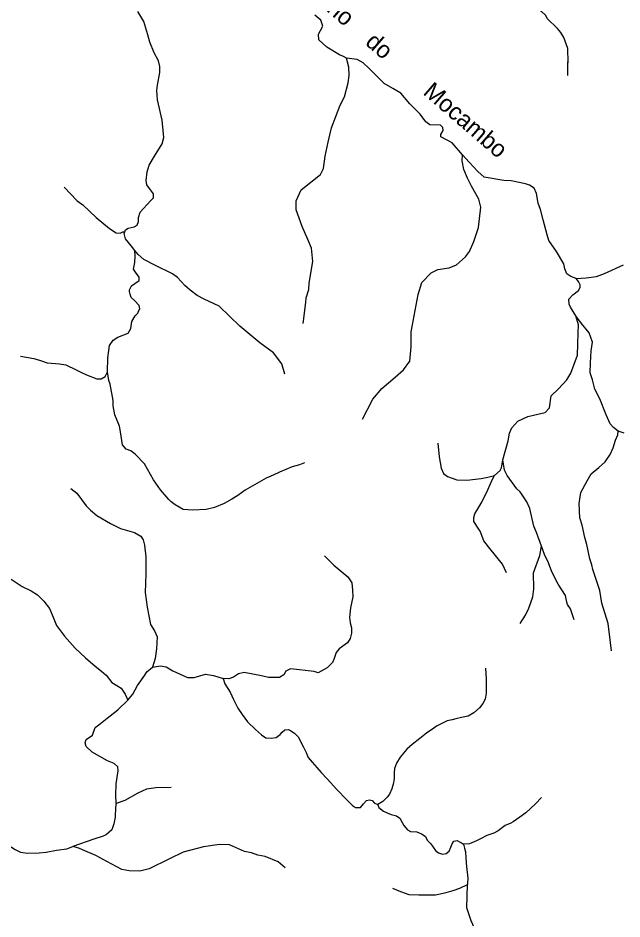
# Model space of a CAD drawing. Extents: x 717.8 to 772.7, y 8672.2 to 8728.
# Drawn here: x 731.87 to 738.93, y 8683.34 to 8693.87 of the extents above; entities that cross this region are included whole.
import ezdxf
from ezdxf.enums import TextEntityAlignment as Align

# ---------------------------------------------------------------- set-up
doc = ezdxf.new("R2010")
doc.units = 0
doc.header["$LTSCALE"] = 0.08
doc.linetypes.add('LONG_DASHED', pattern=[7.5, 6, -1.5])
doc.layers.add('61', color=7, linetype='Continuous')
doc.layers.add('9', color=7, linetype='LONG_DASHED', lineweight=25)

msp = doc.modelspace()

# ---------------------------------------------------------------- linework, layer by layer
at = {"layer": '9'}
for points in [[(738.3015, 8693.1977), (738.2982, 8693.3556), (738.304, 8693.3504), (738.2982, 8693.5135), (738.2535, 8693.6405), (738.2193, 8693.6999), (738.178, 8693.7479), (738.06, 8693.8635), (738.0418, 8693.8992), (737.9893, 8693.9514), (737.9339, 8694.0442), (737.8695, 8694.1113)], [(733.1221, 8691.3695), (733.1323, 8691.394), (733.1632, 8691.4148), (733.2303, 8691.4271), (733.2664, 8691.4478), (733.2827, 8691.4918), (733.2827, 8691.5397), (733.3008, 8691.6019), (733.4219, 8691.7335), (733.4595, 8691.7695), (733.4578, 8691.8151), (733.4115, 8691.8769), (733.3806, 8691.9201), (733.3723, 8691.9714), (733.3823, 8692.0715), (733.4075, 8692.1512), (733.4693, 8692.2554), (733.5582, 8692.3992), (733.5778, 8692.4732), (733.5721, 8692.553), (733.5599, 8692.6751), (733.504, 8692.9141), (733.4963, 8693.0237), (733.5044, 8693.0847), (733.5334, 8693.2335), (733.5305, 8693.3042), (733.5143, 8693.3679), (733.4671, 8693.4639), (733.415, 8693.586), (733.3898, 8693.6731), (733.3466, 8693.8285), (733.2751, 8693.9465)], [(735.712, 8693.3994), (735.6763, 8693.421), (735.6306, 8693.439), (735.484, 8693.5306), (735.3886, 8693.613), (735.3848, 8693.6809), (735.4352, 8693.7759), (735.4123, 8693.8453), (735.342, 8693.9019)], [(735.207, 8690.3005), (735.2379, 8690.5437), (735.2418, 8690.5979), (735.2728, 8690.696), (735.2766, 8690.7696), (735.3202, 8691.0222), (735.3037, 8691.1803), (735.2626, 8691.2797), (735.1968, 8691.4347), (735.1232, 8691.6258), (735.1237, 8691.7347), (735.1824, 8691.8619), (735.4095, 8692.0388), (735.4432, 8692.1098), (735.4645, 8692.2557), (735.4987, 8692.4171), (735.5381, 8692.5849), (735.6375, 8692.8516), (735.6899, 8692.9465), (735.7331, 8693.1118), (735.7434, 8693.1996), (735.7406, 8693.2932), (735.712, 8693.3994)], [(737.0678, 8692.2712), (736.9469, 8692.4102), (736.8818, 8692.4477), (736.8176, 8692.4804), (736.8155, 8692.5096), (736.8425, 8692.5549), (736.8403, 8692.5892), (736.8133, 8692.6162), (736.6862, 8692.6228), (736.6417, 8692.6579), (736.5752, 8692.7448), (736.4547, 8692.8667), (736.3481, 8692.9894), (736.2539, 8693.0456), (736.1519, 8693.1046), (736.0183, 8693.2394), (735.9744, 8693.2835), (735.9092, 8693.3458), (735.8382, 8693.3829), (735.712, 8693.3994)], [(735.9002, 8689.1792), (736.0227, 8689.4132), (736.1266, 8689.5379), (736.284, 8689.6707), (736.3803, 8689.7585), (736.4518, 8689.8586), (736.4673, 8690.0265), (736.4673, 8690.2028), (736.5517, 8690.6364), (736.5922, 8690.7794), (736.7018, 8690.8928), (736.7804, 8690.9286), (736.9131, 8690.9484), (736.9971, 8690.9867), (737.0685, 8691.0458), (737.1024, 8691.0774), (737.1499, 8691.1404), (737.2006, 8691.259), (737.2542, 8691.4217), (737.2842, 8691.6571), (737.2597, 8691.7517), (737.1733, 8691.9038), (737.1262, 8691.997), (737.0847, 8692.0989), (737.0646, 8692.1989), (737.0678, 8692.2712)], [(738.3986, 8690.8265), (738.3332, 8690.8479), (738.2876, 8690.8795), (738.2651, 8690.9368), (738.2518, 8690.9958), (738.1695, 8691.1405), (738.0769, 8691.2706), (738.0589, 8691.3349), (738.01, 8691.51), (737.9808, 8691.6296), (737.9526, 8691.7068), (737.9347, 8691.8179), (737.9072, 8691.8807), (737.8511, 8691.9149), (737.8067, 8691.9326), (737.6378, 8691.9682), (737.5535, 8691.9694), (737.3238, 8692.008), (737.2466, 8692.0754), (737.145, 8692.1841), (737.0678, 8692.2712)], [(732.4125, 8691.8913), (732.5636, 8691.7328), (732.6313, 8691.6862), (732.7871, 8691.5398), (732.9436, 8691.4098), (733.0202, 8691.3607), (733.0673, 8691.3566), (733.0974, 8691.3707), (733.1221, 8691.3695)], [(733.2385, 8691.1517), (733.2014, 8691.2045), (733.131, 8691.289), (733.1145, 8691.3513), (733.1221, 8691.3695)], [(732.9187, 8689.733), (732.9231, 8689.8993), (732.9343, 8689.9835), (732.9447, 8690.0419), (732.9865, 8690.105), (733.0392, 8690.1391), (733.1598, 8690.1864), (733.1934, 8690.2388), (733.2062, 8690.323), (733.2452, 8690.3899), (733.2743, 8690.4208), (733.2826, 8690.4444), (733.2972, 8690.4721), (733.2902, 8690.5111), (733.2349, 8690.5695), (733.1981, 8690.6036), (733.1843, 8690.6436), (733.179, 8690.6725), (733.179, 8690.693), (733.1997, 8690.741), (733.2884, 8690.801), (733.2892, 8690.8409), (733.248, 8690.8973), (733.222, 8690.9334), (733.238, 8691.0126), (733.245, 8691.086), (733.2385, 8691.1517)], [(734.9912, 8689.7073), (734.9579, 8689.8263), (734.8582, 8689.9548), (734.699, 8690.0733), (734.4647, 8690.2683), (734.2236, 8690.5031), (734.0482, 8690.583), (733.9686, 8690.6273), (733.8871, 8690.6901), (733.8254, 8690.7429), (733.7376, 8690.8367), (733.6784, 8690.8786), (733.4731, 8690.9825), (733.3455, 8691.0483), (733.2795, 8691.1038), (733.2385, 8691.1517)], [(738.3986, 8690.8265), (738.5136, 8690.8347), (738.6342, 8690.8468), (738.7273, 8690.8828), (738.9496, 8690.9845)], [(738.3951, 8690.3892), (738.33, 8690.4892), (738.3139, 8690.5263), (738.3131, 8690.582), (738.3588, 8690.6333), (738.4263, 8690.6853), (738.4451, 8690.7196), (738.4424, 8690.7509), (738.4259, 8690.7887), (738.3988, 8690.8265), (738.3986, 8690.8265)], [(737.541, 8688.7043), (737.6033, 8688.9263), (737.6173, 8689.0181), (737.6438, 8689.0801), (737.7169, 8689.1577), (737.8342, 8689.2109), (737.9501, 8689.2412), (738.0356, 8689.2596), (738.0865, 8689.3138), (738.1065, 8689.4533), (738.1906, 8689.5363), (738.2871, 8689.6393), (738.3355, 8689.7169), (738.4115, 8689.9279), (738.4164, 8690.0561), (738.4212, 8690.1918), (738.4257, 8690.2817), (738.3951, 8690.3892)], [(738.8888, 8689.0416), (738.8352, 8689.0824), (738.7964, 8689.1262), (738.7491, 8689.2333), (738.674, 8689.4198), (738.6167, 8689.533), (738.588, 8689.6401), (738.5619, 8689.7228), (738.5642, 8689.8385), (738.5737, 8689.9811), (738.5872, 8690.0816), (738.5491, 8690.1895), (738.4598, 8690.2993), (738.4286, 8690.3407), (738.3951, 8690.3892)], [(731.902, 8689.9162), (732.058, 8689.8901), (732.136, 8689.8667), (732.2143, 8689.8407), (732.359, 8689.8263), (732.4325, 8689.8146), (732.5527, 8689.7577), (732.6097, 8689.7314), (732.674, 8689.6992), (732.7972, 8689.6514), (732.8441, 8689.6526), (732.8936, 8689.6809), (732.9187, 8689.733)], [(735.2222, 8688.671), (735.165, 8688.6487), (735.0776, 8688.6248), (734.9303, 8688.5597), (734.8579, 8688.5273), (734.7759, 8688.4922), (734.528, 8688.3507), (734.443, 8688.2879), (734.3742, 8688.2442), (734.2848, 8688.1962), (734.1705, 8688.1497), (734.0747, 8688.1266), (733.9144, 8688.116), (733.8062, 8688.1258), (733.7126, 8688.1787), (733.6658, 8688.2162), (733.6383, 8688.2436), (733.5401, 8688.3569), (733.4589, 8688.4732), (733.3522, 8688.6605), (733.2449, 8688.7717), (733.1932, 8688.8113), (733.14, 8688.8289), (733.0963, 8688.8814), (733.0718, 8689.0329), (733.0612, 8689.1009), (733.007, 8689.2317), (732.9877, 8689.336), (732.9846, 8689.3987), (732.9502, 8689.5892), (732.9345, 8689.6334), (732.9187, 8689.733)], [(738.8111, 8686.4733), (738.7959, 8686.5998), (738.7697, 8686.7942), (738.6983, 8687.0312), (738.6743, 8687.177), (738.5914, 8687.4244), (738.5821, 8687.4772), (738.5583, 8687.5476), (738.522, 8687.7162), (738.4973, 8687.7991), (738.4669, 8687.9406), (738.439, 8688.0258), (738.4328, 8688.1945), (738.4504, 8688.3229), (738.5279, 8688.4615), (738.5714, 8688.5412), (738.6624, 8688.6155), (738.7379, 8688.683), (738.7943, 8688.768), (738.8312, 8688.8463), (738.8579, 8688.9352), (738.8849, 8688.9971), (738.8888, 8689.0416)], [(738.9581, 8689.0162), (738.8888, 8689.0416)], [(736.7802, 8688.9016), (736.7953, 8688.7418), (736.8183, 8688.6095), (736.8467, 8688.5447), (736.892, 8688.5101), (737.0029, 8688.4719), (737.1201, 8688.4674), (737.2878, 8688.4869), (737.3639, 8688.5027), (737.4425, 8688.5207)], [(737.4425, 8688.5207), (737.5094, 8688.58), (737.5266, 8688.6131), (737.541, 8688.7043)], [(737.9907, 8687.6971), (737.9352, 8687.8555), (737.9029, 8687.9312), (737.8574, 8688.135), (737.8195, 8688.2135), (737.7449, 8688.3334), (737.7059, 8688.3671), (737.5925, 8688.5237), (737.5581, 8688.5858), (737.541, 8688.7043)], [(737.5841, 8687.3861), (737.538, 8687.4864), (737.4687, 8687.5672), (737.3728, 8687.6888), (737.3193, 8687.7608), (737.2754, 8687.8714), (737.2582, 8687.896), (737.1998, 8687.9836), (737.2015, 8688.0315), (737.2138, 8688.0758), (737.294, 8688.2117), (737.3651, 8688.3556), (737.4183, 8688.4781), (737.4425, 8688.5207)], [(732.4932, 8688.3724), (732.5621, 8688.317), (732.6725, 8688.1668), (732.7198, 8688.1178), (732.7951, 8688.0537), (732.9545, 8687.96), (733.0708, 8687.904), (733.1553, 8687.8809), (733.2371, 8687.8561), (733.3108, 8687.813), (733.3378, 8687.77), (733.3534, 8687.7091), (733.3685, 8687.5712), (733.3679, 8687.3747), (733.3612, 8687.1565), (733.3828, 8686.982), (733.4231, 8686.7824), (733.4677, 8686.7076), (733.5013, 8686.6374), (733.4945, 8686.4947), (733.4758, 8686.3832), (733.4479, 8686.281)], [(737.7412, 8686.7936), (737.8035, 8686.89), (737.8433, 8686.9726), (737.8895, 8687.105), (737.9043, 8687.198), (737.8997, 8687.3845), (737.9733, 8687.5887), (737.9907, 8687.6971)], [(738.3751, 8686.8372), (738.3306, 8686.9624), (738.2967, 8687.0147), (738.2892, 8687.0439), (738.2731, 8687.118), (738.1876, 8687.2532), (738.1146, 8687.3965), (738.0755, 8687.5007), (738.0284, 8687.5972), (737.9907, 8687.6971)], [(735.4571, 8687.5838), (735.5669, 8687.474), (735.6347, 8687.4164), (735.7282, 8687.3368), (735.7749, 8687.2677), (735.7843, 8687.184), (735.7863, 8687.1041), (735.7582, 8686.975), (735.749, 8686.8616), (735.7578, 8686.8012), (735.7716, 8686.7424), (735.771, 8686.6805), (735.7569, 8686.6163), (735.7251, 8686.5662), (735.6284, 8686.4961), (735.5911, 8686.4533), (735.5699, 8686.3842), (735.5513, 8686.3377), (735.4858, 8686.2726), (735.3838, 8686.2164), (735.3356, 8686.2317), (735.058, 8686.2625), (735.0031, 8686.2372), (734.9823, 8686.1922), (734.9318, 8686.1604), (734.8013, 8686.1604), (734.7196, 8686.1793), (734.5173, 8686.2185), (734.4514, 8686.2032), (734.3922, 8686.1636), (734.3395, 8686.1461), (734.2714, 8686.1499)], [(731.7934, 8687.31), (731.9221, 8687.2261), (732.027, 8687.1755), (732.1011, 8687.1264), (732.1776, 8687.0525), (732.2414, 8686.9685), (732.2844, 8686.8665), (732.3245, 8686.7711), (732.4193, 8686.6432), (732.5409, 8686.5038), (732.6626, 8686.3923), (732.7762, 8686.2931), (732.8486, 8686.2371), (732.9058, 8686.1879), (732.9725, 8686.1021), (733.0285, 8686.0681), (733.079, 8686.0374), (733.1283, 8685.9682), (733.1561, 8685.8978)], [(733.4479, 8686.281), (733.5398, 8686.2974), (733.6067, 8686.2843), (733.6852, 8686.2381), (733.8558, 8686.1625), (733.9337, 8686.1625), (734.0664, 8686.1988), (734.1592, 8686.1867), (734.2714, 8686.1499)], [(733.1561, 8685.8978), (733.2163, 8685.9649), (733.2707, 8686.069), (733.3579, 8686.1907), (733.3784, 8686.2263), (733.4479, 8686.281)], [(737.3379, 8686.2722), (737.3457, 8686.1435), (737.3457, 8686.0458), (737.3457, 8685.9794), (737.3326, 8685.91), (737.3058, 8685.8581), (737.2658, 8685.8055), (737.2026, 8685.7479), (737.1365, 8685.7078), (737.0571, 8685.693), (736.9897, 8685.6779), (736.9473, 8685.6679), (736.8896, 8685.6554), (736.8265, 8685.6248), (736.764, 8685.5938), (736.7323, 8685.5678), (736.6482, 8685.511), (736.5701, 8685.4503), (736.4798, 8685.3802), (736.4193, 8685.3257), (736.3397, 8685.2291), (736.297, 8685.1612), (736.2761, 8685.0975), (736.2694, 8685.0453), (736.2687, 8684.9774), (736.2568, 8684.9153), (736.2437, 8684.8585), (736.217, 8684.7978), (736.189, 8684.7613), (736.1363, 8684.7141), (736.0779, 8684.6758)], [(734.2714, 8686.1499), (734.2921, 8686.087), (734.3518, 8685.9891), (734.3945, 8685.904), (734.4447, 8685.804), (734.4924, 8685.729), (734.5576, 8685.6415), (734.6479, 8685.5539), (734.7181, 8685.4914), (734.7707, 8685.4564), (734.8309, 8685.4514), (734.891, 8685.4614), (734.9361, 8685.4966), (734.9624, 8685.524), (734.9943, 8685.5481), (735.0349, 8685.5525), (735.0512, 8685.5441), (735.1063, 8685.5115), (735.1489, 8685.4665), (735.2103, 8685.349), (735.2404, 8685.2839), (735.2656, 8685.2264), (735.3106, 8685.1714), (735.3657, 8685.1114), (735.4184, 8685.0513), (735.4885, 8684.9763), (735.6013, 8684.8513), (735.7128, 8684.7339), (735.782, 8684.6669), (735.8193, 8684.6417), (735.8763, 8684.6439), (735.9128, 8684.6861), (735.9453, 8684.7236), (735.984, 8684.7327), (736.0117, 8684.7244), (736.0424, 8684.693), (736.0779, 8684.6758)], [(733.0199, 8684.6869), (733.0164, 8684.7876), (733.0219, 8684.9195), (733.0463, 8685.069), (733.0406, 8685.1187), (732.9961, 8685.1551), (732.9189, 8685.1894), (732.8293, 8685.238), (732.7397, 8685.2896), (732.671, 8685.3544), (732.6599, 8685.3987), (732.6726, 8685.4384), (732.7454, 8685.486), (732.7763, 8685.5777), (732.8169, 8685.6072), (732.9161, 8685.6848), (733.039, 8685.7827), (733.1561, 8685.8978)], [(733.6653, 8684.8747), (733.4838, 8684.8726), (733.3769, 8684.8561), (733.2749, 8684.8105), (733.1239, 8684.723), (733.0199, 8684.6869)], [(737.9923, 8684.759), (737.9249, 8684.689), (737.865, 8684.6289), (737.8075, 8684.5815), (737.74, 8684.5289), (737.6626, 8684.474), (737.6347, 8684.4582), (737.5667, 8684.433), (737.4866, 8684.3704), (737.4361, 8684.343), (737.3516, 8684.3133), (737.2803, 8684.276), (737.232, 8684.2511), (737.1492, 8684.2176), (737.0792, 8684.215)], [(733.0199, 8684.6869), (733.0133, 8684.6467), (733.0094, 8684.529), (732.994, 8684.4528), (732.9721, 8684.3804), (732.91, 8684.3251), (732.8693, 8684.3062), (732.7607, 8684.2708), (732.5151, 8684.1857)], [(736.0779, 8684.6758), (736.0804, 8684.6736), (736.0925, 8684.6439), (736.1451, 8684.601), (736.1905, 8684.5785), (736.2354, 8684.5585), (736.298, 8684.5435), (736.3379, 8684.5184), (736.3656, 8684.4671), (736.3843, 8684.4298), (736.4249, 8684.3804), (736.4622, 8684.3629), (736.5354, 8684.3557), (736.5903, 8684.3357), (736.6328, 8684.3057), (736.6618, 8684.2574), (736.6977, 8684.2156), (736.7277, 8684.178), (736.7517, 8684.1389), (736.7868, 8684.1125), (736.834, 8684.0983), (736.8763, 8684.1043), (736.9124, 8684.1299), (736.9323, 8684.1799), (736.9473, 8684.2174), (736.9674, 8684.2499), (737.0049, 8684.2565), (737.0334, 8684.2418), (737.0581, 8684.2275), (737.0792, 8684.215)], [(731.3065, 8684.5331), (731.3398, 8684.5169), (731.4236, 8684.4419), (731.5237, 8684.3781), (731.6168, 8684.3219), (731.677, 8684.2741), (731.7431, 8684.2136), (731.8395, 8684.1503), (731.9034, 8684.1205), (731.9866, 8684.1089), (732.1232, 8684.1122), (732.2046, 8684.1213), (732.3243, 8684.1435), (732.4444, 8684.1606), (732.5151, 8684.1857)], [(734.9977, 8683.9355), (734.9155, 8684.0058), (734.7625, 8684.0685), (734.6784, 8684.0834), (734.6029, 8684.1111), (734.522, 8684.127), (734.3464, 8684.2058), (734.2298, 8684.2086), (734.0413, 8684.1826), (733.8057, 8684.1202), (733.6441, 8684.042), (733.4089, 8683.927), (733.2962, 8683.8982), (733.1739, 8683.9021), (733.0884, 8683.9174), (732.9105, 8684.0112), (732.7838, 8684.0801), (732.6278, 8684.1465), (732.5849, 8684.1683), (732.5151, 8684.1857)], [(737.0792, 8684.215), (737.0922, 8684.1648), (737.1046, 8684.1222), (737.107, 8684.0547), (737.1119, 8683.9947), (737.1144, 8683.9521), (737.1304, 8683.817), (737.1278, 8683.757), (737.1292, 8683.7407)], [(736.2498, 8683.6987), (736.3442, 8683.659), (736.443, 8683.6257), (736.5583, 8683.6198), (736.7516, 8683.6207), (736.8788, 8683.6482), (736.9589, 8683.6723), (737.039, 8683.6975), (737.1292, 8683.7407)], [(737.9202, 8681.1573), (737.8838, 8681.2495), (737.8543, 8681.3846), (737.815, 8681.4999), (737.7641, 8681.6215), (737.7713, 8681.7676), (737.7871, 8681.8092), (737.8391, 8681.9464), (737.84, 8681.9778), (737.8265, 8682.0297), (737.7148, 8682.205), (737.6181, 8682.3421), (737.5832, 8682.4181), (737.5466, 8682.5443), (737.484, 8682.6454), (737.4339, 8682.7054), (737.3838, 8682.9496), (737.3337, 8683.0355), (737.2438, 8683.1546), (737.1688, 8683.3181), (737.1208, 8683.4696), (737.1292, 8683.7407)]]:
    msp.add_lwpolyline(points, dxfattribs=at)

# ---------------------------------------------------------------- texts
at = {"layer": '61'}
msp.add_text('Riacho    do        Mocambo', height=0.2, rotation=319.253, dxfattribs=at).set_placement((736.2762, 8693.2622), align=Align.CENTER)

doc.saveas('drawing.dxf')
